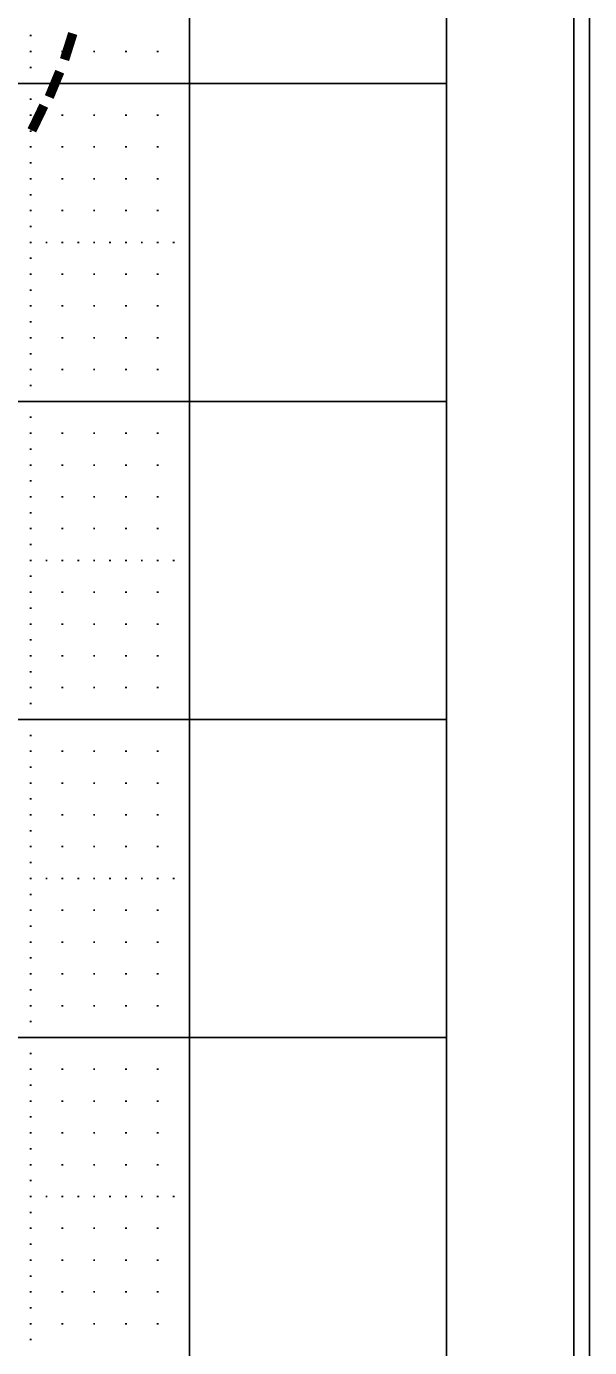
# Model space of a CAD drawing. Extents: x -3.6 to 32.1, y -0.4 to 25.6.
# Drawn here: x 30.295 to 32.067, y 12.57 to 16.724 of the extents above; entities that cross this region are included whole.
import ezdxf

# ---------------------------------------------------------------- set-up
doc = ezdxf.new("R2010")
doc.units = 0
for name, color, linetype in [('Level 4', 7, 'Continuous'), ('Level 5', 7, 'Continuous'), ('Level 62', 7, 'Continuous'), ('Level 63', 7, 'Continuous'), ('Level 63 Full', 7, 'Continuous'), ('R_Border Prelim', 7, 'Continuous'), ('R_Border Prem', 7, 'Continuous')]:
    doc.layers.add(name, color=color, linetype=linetype)

msp = doc.modelspace()

# ---------------------------------------------------------------- linework, layer by layer
at = {"layer": 'Level 4'}
for p, q in [((30.808, 0.545), (30.808, 19.545)), ((31.617, 16.545), (-0.001, 16.545)), ((31.617, 15.545), (-0.001, 15.545)), ((31.617, 14.545), (-0.001, 14.545)), ((31.617, 13.545), (-0.001, 13.545))]:
    msp.add_line(p, q, dxfattribs=at)
at = {"layer": 'Level 5'}
for p, q in [((30.3055, 16.695), (30.3105, 16.695)), ((30.3055, 16.645), (30.3105, 16.645)), ((30.4055, 16.645), (30.4105, 16.645)), ((30.5055, 16.645), (30.5105, 16.645)), ((30.6055, 16.645), (30.6105, 16.645)), ((30.7055, 16.645), (30.7105, 16.645)), ((30.3055, 16.595), (30.3105, 16.595)), ((30.3055, 16.495), (30.3105, 16.495)), ((30.3055, 16.445), (30.3105, 16.445)), ((30.4055, 16.445), (30.4105, 16.445)), ((30.5055, 16.445), (30.5105, 16.445)), ((30.6055, 16.445), (30.6105, 16.445)), ((30.7055, 16.445), (30.7105, 16.445)), ((30.3055, 16.395), (30.3105, 16.395)), ((30.3055, 16.345), (30.3105, 16.345)), ((30.4055, 16.345), (30.4105, 16.345)), ((30.5055, 16.345), (30.5105, 16.345)), ((30.6055, 16.345), (30.6105, 16.345)), ((30.7055, 16.345), (30.7105, 16.345)), ((30.3055, 16.295), (30.3105, 16.295)), ((30.3055, 16.245), (30.3105, 16.245)), ((30.4055, 16.245), (30.4105, 16.245)), ((30.5055, 16.245), (30.5105, 16.245)), ((30.6055, 16.245), (30.6105, 16.245)), ((30.7055, 16.245), (30.7105, 16.245)), ((30.3055, 16.195), (30.3105, 16.195)), ((30.3055, 16.145), (30.3105, 16.145)), ((30.4055, 16.145), (30.4105, 16.145)), ((30.5055, 16.145), (30.5105, 16.145)), ((30.6055, 16.145), (30.6105, 16.145)), ((30.7055, 16.145), (30.7105, 16.145)), ((30.3055, 16.095), (30.3105, 16.095)), ((30.3055, 16.045), (30.3105, 16.045)), ((30.3555, 16.045), (30.3605, 16.045)), ((30.4055, 16.045), (30.4105, 16.045)), ((30.4555, 16.045), (30.4605, 16.045)), ((30.5055, 16.045), (30.5105, 16.045)), ((30.5555, 16.045), (30.5605, 16.045)), ((30.6055, 16.045), (30.6105, 16.045)), ((30.6555, 16.045), (30.6605, 16.045)), ((30.7055, 16.045), (30.7105, 16.045)), ((30.7555, 16.045), (30.7605, 16.045)), ((30.3055, 15.995), (30.3105, 15.995)), ((30.3055, 15.945), (30.3105, 15.945)), ((30.4055, 15.945), (30.4105, 15.945)), ((30.5055, 15.945), (30.5105, 15.945)), ((30.6055, 15.945), (30.6105, 15.945)), ((30.7055, 15.945), (30.7105, 15.945)), ((30.3055, 15.895), (30.3105, 15.895)), ((30.3055, 15.845), (30.3105, 15.845)), ((30.4055, 15.845), (30.4105, 15.845)), ((30.5055, 15.845), (30.5105, 15.845)), ((30.6055, 15.845), (30.6105, 15.845)), ((30.7055, 15.845), (30.7105, 15.845)), ((30.3055, 15.795), (30.3105, 15.795)), ((30.3055, 15.745), (30.3105, 15.745)), ((30.4055, 15.745), (30.4105, 15.745)), ((30.5055, 15.745), (30.5105, 15.745)), ((30.6055, 15.745), (30.6105, 15.745)), ((30.7055, 15.745), (30.7105, 15.745)), ((30.3055, 15.695), (30.3105, 15.695)), ((30.3055, 15.645), (30.3105, 15.645)), ((30.4055, 15.645), (30.4105, 15.645)), ((30.5055, 15.645), (30.5105, 15.645)), ((30.6055, 15.645), (30.6105, 15.645)), ((30.7055, 15.645), (30.7105, 15.645)), ((30.3055, 15.595), (30.3105, 15.595)), ((30.3055, 15.495), (30.3105, 15.495)), ((30.3055, 15.445), (30.3105, 15.445)), ((30.4055, 15.445), (30.4105, 15.445)), ((30.5055, 15.445), (30.5105, 15.445)), ((30.6055, 15.445), (30.6105, 15.445)), ((30.7055, 15.445), (30.7105, 15.445)), ((30.3055, 15.395), (30.3105, 15.395)), ((30.3055, 15.345), (30.3105, 15.345)), ((30.4055, 15.345), (30.4105, 15.345)), ((30.5055, 15.345), (30.5105, 15.345)), ((30.6055, 15.345), (30.6105, 15.345)), ((30.7055, 15.345), (30.7105, 15.345)), ((30.3055, 15.295), (30.3105, 15.295)), ((30.3055, 15.245), (30.3105, 15.245)), ((30.4055, 15.245), (30.4105, 15.245)), ((30.5055, 15.245), (30.5105, 15.245)), ((30.6055, 15.245), (30.6105, 15.245)), ((30.7055, 15.245), (30.7105, 15.245)), ((30.3055, 15.195), (30.3105, 15.195)), ((30.3055, 15.145), (30.3105, 15.145)), ((30.4055, 15.145), (30.4105, 15.145)), ((30.5055, 15.145), (30.5105, 15.145)), ((30.6055, 15.145), (30.6105, 15.145)), ((30.7055, 15.145), (30.7105, 15.145)), ((30.3055, 15.095), (30.3105, 15.095)), ((30.3055, 15.045), (30.3105, 15.045)), ((30.3555, 15.045), (30.3605, 15.045)), ((30.4055, 15.045), (30.4105, 15.045)), ((30.4555, 15.045), (30.4605, 15.045)), ((30.5055, 15.045), (30.5105, 15.045)), ((30.5555, 15.045), (30.5605, 15.045)), ((30.6055, 15.045), (30.6105, 15.045)), ((30.6555, 15.045), (30.6605, 15.045)), ((30.7055, 15.045), (30.7105, 15.045)), ((30.7555, 15.045), (30.7605, 15.045)), ((30.3055, 14.995), (30.3105, 14.995)), ((30.3055, 14.945), (30.3105, 14.945)), ((30.4055, 14.945), (30.4105, 14.945)), ((30.5055, 14.945), (30.5105, 14.945)), ((30.6055, 14.945), (30.6105, 14.945)), ((30.7055, 14.945), (30.7105, 14.945)), ((30.3055, 14.895), (30.3105, 14.895)), ((30.3055, 14.845), (30.3105, 14.845)), ((30.4055, 14.845), (30.4105, 14.845)), ((30.5055, 14.845), (30.5105, 14.845)), ((30.6055, 14.845), (30.6105, 14.845)), ((30.7055, 14.845), (30.7105, 14.845)), ((30.3055, 14.795), (30.3105, 14.795)), ((30.3055, 14.745), (30.3105, 14.745)), ((30.4055, 14.745), (30.4105, 14.745)), ((30.5055, 14.745), (30.5105, 14.745)), ((30.6055, 14.745), (30.6105, 14.745)), ((30.7055, 14.745), (30.7105, 14.745)), ((30.3055, 14.695), (30.3105, 14.695)), ((30.3055, 14.645), (30.3105, 14.645)), ((30.4055, 14.645), (30.4105, 14.645)), ((30.5055, 14.645), (30.5105, 14.645)), ((30.6055, 14.645), (30.6105, 14.645)), ((30.7055, 14.645), (30.7105, 14.645)), ((30.3055, 14.595), (30.3105, 14.595)), ((30.3055, 14.495), (30.3105, 14.495)), ((30.3055, 14.445), (30.3105, 14.445)), ((30.4055, 14.445), (30.4105, 14.445)), ((30.5055, 14.445), (30.5105, 14.445)), ((30.6055, 14.445), (30.6105, 14.445)), ((30.7055, 14.445), (30.7105, 14.445)), ((30.3055, 14.395), (30.3105, 14.395)), ((30.3055, 14.345), (30.3105, 14.345)), ((30.4055, 14.345), (30.4105, 14.345)), ((30.5055, 14.345), (30.5105, 14.345)), ((30.6055, 14.345), (30.6105, 14.345)), ((30.7055, 14.345), (30.7105, 14.345)), ((30.3055, 14.295), (30.3105, 14.295)), ((30.3055, 14.245), (30.3105, 14.245)), ((30.4055, 14.245), (30.4105, 14.245)), ((30.5055, 14.245), (30.5105, 14.245)), ((30.6055, 14.245), (30.6105, 14.245)), ((30.7055, 14.245), (30.7105, 14.245)), ((30.3055, 14.195), (30.3105, 14.195)), ((30.3055, 14.145), (30.3105, 14.145)), ((30.4055, 14.145), (30.4105, 14.145)), ((30.5055, 14.145), (30.5105, 14.145)), ((30.6055, 14.145), (30.6105, 14.145)), ((30.7055, 14.145), (30.7105, 14.145)), ((30.3055, 14.095), (30.3105, 14.095)), ((30.3055, 14.045), (30.3105, 14.045)), ((30.3555, 14.045), (30.3605, 14.045)), ((30.4055, 14.045), (30.4105, 14.045)), ((30.4555, 14.045), (30.4605, 14.045)), ((30.5055, 14.045), (30.5105, 14.045)), ((30.5555, 14.045), (30.5605, 14.045)), ((30.6055, 14.045), (30.6105, 14.045)), ((30.6555, 14.045), (30.6605, 14.045)), ((30.7055, 14.045), (30.7105, 14.045)), ((30.7555, 14.045), (30.7605, 14.045)), ((30.3055, 13.995), (30.3105, 13.995)), ((30.3055, 13.945), (30.3105, 13.945)), ((30.4055, 13.945), (30.4105, 13.945)), ((30.5055, 13.945), (30.5105, 13.945)), ((30.6055, 13.945), (30.6105, 13.945)), ((30.7055, 13.945), (30.7105, 13.945)), ((30.3055, 13.895), (30.3105, 13.895)), ((30.3055, 13.845), (30.3105, 13.845)), ((30.4055, 13.845), (30.4105, 13.845)), ((30.5055, 13.845), (30.5105, 13.845)), ((30.6055, 13.845), (30.6105, 13.845)), ((30.7055, 13.845), (30.7105, 13.845)), ((30.3055, 13.795), (30.3105, 13.795)), ((30.3055, 13.745), (30.3105, 13.745)), ((30.4055, 13.745), (30.4105, 13.745)), ((30.5055, 13.745), (30.5105, 13.745)), ((30.6055, 13.745), (30.6105, 13.745)), ((30.7055, 13.745), (30.7105, 13.745)), ((30.3055, 13.695), (30.3105, 13.695)), ((30.3055, 13.645), (30.3105, 13.645)), ((30.4055, 13.645), (30.4105, 13.645)), ((30.5055, 13.645), (30.5105, 13.645)), ((30.6055, 13.645), (30.6105, 13.645)), ((30.7055, 13.645), (30.7105, 13.645)), ((30.3055, 13.595), (30.3105, 13.595)), ((30.3055, 13.495), (30.3105, 13.495)), ((30.3055, 13.445), (30.3105, 13.445)), ((30.4055, 13.445), (30.4105, 13.445)), ((30.5055, 13.445), (30.5105, 13.445)), ((30.6055, 13.445), (30.6105, 13.445)), ((30.7055, 13.445), (30.7105, 13.445)), ((30.3055, 13.395), (30.3105, 13.395)), ((30.3055, 13.345), (30.3105, 13.345)), ((30.4055, 13.345), (30.4105, 13.345)), ((30.5055, 13.345), (30.5105, 13.345)), ((30.6055, 13.345), (30.6105, 13.345)), ((30.7055, 13.345), (30.7105, 13.345)), ((30.3055, 13.295), (30.3105, 13.295)), ((30.3055, 13.245), (30.3105, 13.245)), ((30.4055, 13.245), (30.4105, 13.245)), ((30.5055, 13.245), (30.5105, 13.245)), ((30.6055, 13.245), (30.6105, 13.245)), ((30.7055, 13.245), (30.7105, 13.245)), ((30.3055, 13.195), (30.3105, 13.195)), ((30.3055, 13.145), (30.3105, 13.145)), ((30.4055, 13.145), (30.4105, 13.145)), ((30.5055, 13.145), (30.5105, 13.145)), ((30.6055, 13.145), (30.6105, 13.145)), ((30.7055, 13.145), (30.7105, 13.145)), ((30.3055, 13.095), (30.3105, 13.095)), ((30.3055, 13.045), (30.3105, 13.045)), ((30.3555, 13.045), (30.3605, 13.045)), ((30.4055, 13.045), (30.4105, 13.045)), ((30.4555, 13.045), (30.4605, 13.045)), ((30.5055, 13.045), (30.5105, 13.045)), ((30.5555, 13.045), (30.5605, 13.045)), ((30.6055, 13.045), (30.6105, 13.045)), ((30.6555, 13.045), (30.6605, 13.045)), ((30.7055, 13.045), (30.7105, 13.045)), ((30.7555, 13.045), (30.7605, 13.045)), ((30.3055, 12.995), (30.3105, 12.995)), ((30.3055, 12.945), (30.3105, 12.945)), ((30.4055, 12.945), (30.4105, 12.945)), ((30.5055, 12.945), (30.5105, 12.945)), ((30.6055, 12.945), (30.6105, 12.945)), ((30.7055, 12.945), (30.7105, 12.945)), ((30.3055, 12.895), (30.3105, 12.895)), ((30.3055, 12.845), (30.3105, 12.845)), ((30.4055, 12.845), (30.4105, 12.845)), ((30.5055, 12.845), (30.5105, 12.845)), ((30.6055, 12.845), (30.6105, 12.845)), ((30.7055, 12.845), (30.7105, 12.845)), ((30.3055, 12.795), (30.3105, 12.795)), ((30.3055, 12.745), (30.3105, 12.745)), ((30.4055, 12.745), (30.4105, 12.745)), ((30.5055, 12.745), (30.5105, 12.745)), ((30.6055, 12.745), (30.6105, 12.745)), ((30.7055, 12.745), (30.7105, 12.745)), ((30.3055, 12.695), (30.3105, 12.695)), ((30.3055, 12.645), (30.3105, 12.645)), ((30.4055, 12.645), (30.4105, 12.645)), ((30.5055, 12.645), (30.5105, 12.645)), ((30.6055, 12.645), (30.6105, 12.645)), ((30.7055, 12.645), (30.7105, 12.645)), ((30.3055, 12.595), (30.3105, 12.595))]:
    msp.add_line(p, q, dxfattribs=at)
at = {"layer": 'Level 62'}
msp.add_line((30.808, 0.545), (30.8075, 19.5579), dxfattribs=at)
at = {"layer": 'Level 63'}
msp.add_lwpolyline([(-1.263, -0.2005), (32.067, -0.2005), (32.067, 20.7465), (-1.263, 20.7465)], close=True, dxfattribs=at)
at = {"layer": 'Level 63 Full'}
msp.add_lwpolyline([(32.017, -0.403), (-3.583, -0.403), (-3.583, 20.947), (32.017, 20.947)], close=True, dxfattribs=at)
at = {"layer": 'R_Border Prem'}
msp.add_line((31.617, 20.545), (31.617, -0.001), dxfattribs=at)

# ---------------------------------------------------------------- texts
at = {"layer": 'R_Border Prelim'}
for rotation, p in [(252.4705, (30.3481, 16.7476)), (247.4911, (30.3114, 16.6354)), (244.2221, (30.2645, 16.5334))]:
    msp.add_text('-', height=0.2644, rotation=rotation, dxfattribs=at).set_placement(p)

doc.saveas('drawing.dxf')
